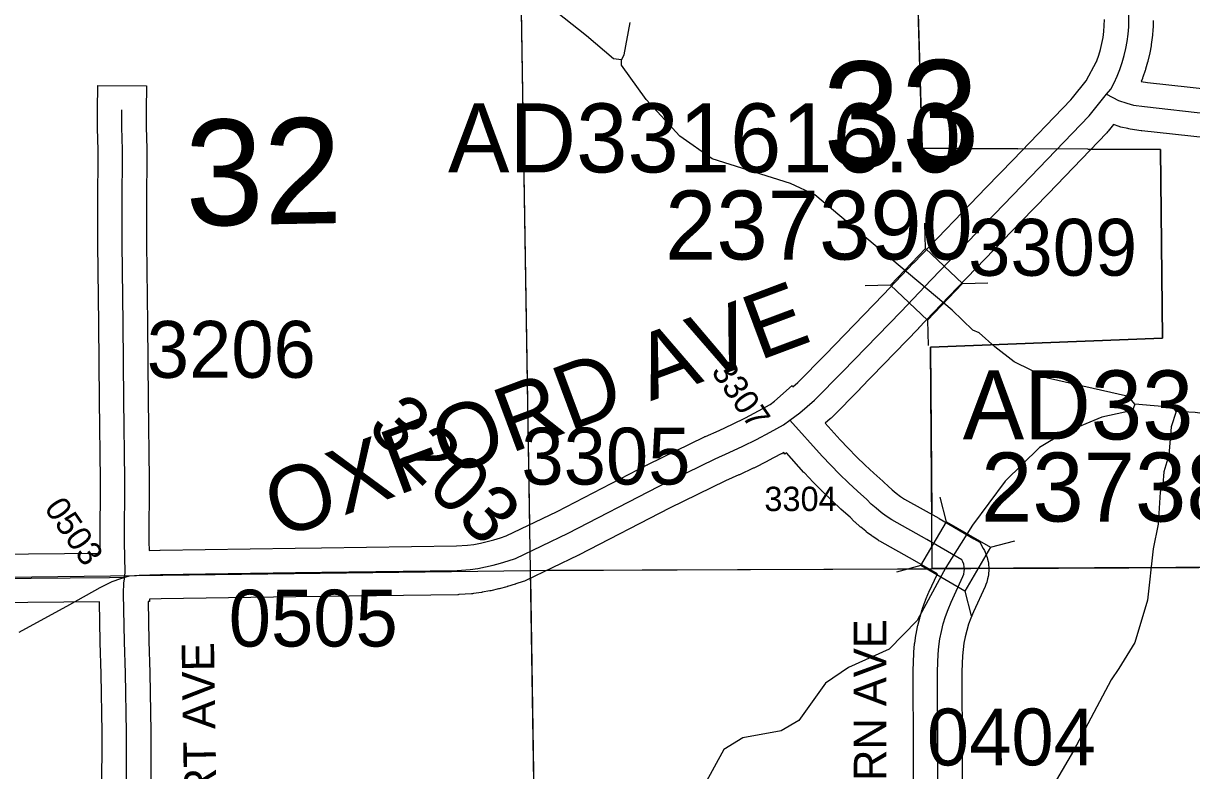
# Model space of a CAD drawing. Extents: x 23.6 to 68.7, y -63 to -29.
# Drawn here: x 46.003 to 47.442, y -45.832 to -44.911 of the extents above; entities that cross this region are included whole.
import ezdxf

# ---------------------------------------------------------------- set-up
doc = ezdxf.new("R2010")
doc.units = 0
for name, color, linetype in [('tdCoHydroRiver', 7, 'Continuous'), ('tdCoSecRdNmbr', 7, 'Continuous'), ('tdCoSecRdTxt', 7, 'Continuous'), ('tdCoSecRteBand', 7, 'Continuous'), ('tdCoSecRteCL', 7, 'Continuous'), ('tdCoSectLine', 7, 'Continuous'), ('tdCoSectLinePart', 7, 'Continuous'), ('tdCoSectNmbr', 7, 'Continuous'), ('tdCoStrucSec', 7, 'Continuous'), ('tdCoStrucSecCoName', 7, 'Continuous'), ('tdCoStrucSecFHWANum', 7, 'Continuous'), ('tdCoSurfAsphalt', 7, 'Continuous'), ('tdCoSurfConc', 7, 'Continuous'), ('tdCoSurfGravel', 7, 'Continuous'), ('tdCoSurfLNO', 7, 'Continuous'), ('tdCoTwpBndry', 7, 'Continuous'), ('tdCoTwpBndryShd', 7, 'Continuous')]:
    doc.layers.add(name, color=color, linetype=linetype)

msp = doc.modelspace()

# ---------------------------------------------------------------- linework, layer by layer
at = {"layer": 'tdCoHydroRiver'}
for points in [[(46.7396, -44.9563), (46.7301, -44.9548), (46.6967, -44.9267), (46.5279, -44.7928), (46.5247, -44.7881)], [(46.7501, -44.9104), (46.7427, -44.9499), (46.7396, -44.9563)], [(47.3725, -45.3803), (47.3645, -45.3709), (47.2648, -45.3483), (47.2235, -45.3282), (47.1997, -45.3096), (47.1805, -45.2924), (47.1726, -45.2893), (47.1471, -45.2644), (46.9782, -45.1226), (46.948, -45.1087), (46.8514, -45.0782), (46.8117, -45.0502), (46.7701, -45.0049), (46.7397, -44.9626), (46.7396, -44.9563)], [(47.3725, -45.3803), (47.3694, -45.3882), (47.3316, -45.3965), (47.2845, -45.416), (47.2547, -45.4337), (47.2125, -45.4752), (47.1721, -45.5293), (47.1395, -45.5817), (47.1039, -45.6468), (47.0695, -45.6819), (47.0193, -45.7046), (46.9911, -45.7238), (46.9584, -45.77), (46.9365, -45.7828), (46.8892, -45.7913), (46.8657, -45.8057), (46.8301, -45.8708)], [(47.4231, -45.3892), (47.4199, -45.3845), (47.3725, -45.3803)], [(47.4231, -45.3892), (47.417, -45.4082), (47.4142, -45.443), (47.4081, -45.4635), (47.4067, -45.4793), (47.4037, -45.4888), (47.4009, -45.5283), (47.395, -45.5584), (47.3877, -45.6216), (47.3725, -45.6739), (47.3524, -45.7057), (47.343, -45.72), (47.2966, -45.8073), (47.2378, -45.9074)], [(47.9026, -45.5023), (47.882, -45.4947), (47.8438, -45.4682), (47.7899, -45.4467), (47.714, -45.4302), (47.4468, -45.3905), (47.4231, -45.3892)]]:
    msp.add_lwpolyline(points, dxfattribs=at)
at = {"layer": 'tdCoSecRteBand'}
for points in [[(45.6545, -45.5678), (46.0979, -45.5638), (46.0976, -45.5509), (46.0976, -45.5505), (46.0976, -45.5501), (46.098, -45.4734), (46.0966, -45.3758), (46.0966, -45.3757), (46.0966, -45.3757), (46.0958, -45.2816), (46.0947, -45.1829), (46.0947, -45.1828), (46.0947, -45.1826), (46.0947, -45.1368), (46.0947, -45.1367), (46.0947, -45.1366), (46.0951, -45.0674), (46.0941, -45.0403), (46.0941, -45.0396), (46.0941, -45.0389), (46.0943, -45.0177), (46.0946, -44.9877), (46.1546, -44.9883), (46.1543, -45.0183), (46.1541, -45.0388), (46.1551, -45.0658), (46.1551, -45.0665), (46.1551, -45.0671), (46.1547, -45.1369), (46.1547, -45.1825), (46.1558, -45.281), (46.1558, -45.281), (46.1558, -45.281), (46.1566, -45.375), (46.158, -45.4728), (46.158, -45.4731), (46.158, -45.4734), (46.1576, -45.55), (46.1578, -45.5605), (46.171, -45.5601), (46.1712, -45.5601), (46.1715, -45.5601), (46.3377, -45.5578), (46.3378, -45.5578), (46.3378, -45.5578), (46.3703, -45.5574), (46.5364, -45.555), (46.55, -45.5541), (46.5577, -45.553), (46.5661, -45.5514), (46.5744, -45.5495), (46.5826, -45.5474), (46.5908, -45.5449), (46.5977, -45.5425), (46.6606, -45.5126), (46.7715, -45.4551), (46.7718, -45.4549), (46.7721, -45.4548), (46.842, -45.4206), (46.8426, -45.4203), (46.8432, -45.42), (46.86, -45.4127), (46.8764, -45.405), (46.8926, -45.397), (46.9085, -45.3886), (46.9229, -45.3807), (46.9285, -45.3765), (46.9499, -45.3575), (46.951, -45.3588), (46.9572, -45.3535), (46.9906, -45.3197), (47.0625, -45.2454), (47.0996, -45.2064), (47.0997, -45.2063), (47.0998, -45.2062), (47.1892, -45.1135), (47.1892, -45.1135), (47.1893, -45.1134), (47.2223, -45.0794), (47.2936, -45.0053), (47.2953, -45.0032), (47.3124, -44.982), (47.3252, -44.9581), (47.3254, -44.9582), (47.3256, -44.9575), (47.3281, -44.9505), (47.3301, -44.9433), (47.3318, -44.9361), (47.3332, -44.9288), (47.3341, -44.9214), (47.3347, -44.914), (47.335, -44.9064)], [(47.395, -44.9078), (47.3947, -44.9167), (47.3947, -44.9174), (47.3946, -44.9182), (47.3939, -44.9271), (47.3938, -44.9278), (47.3937, -44.9286), (47.3925, -44.9374), (47.3924, -44.9381), (47.3923, -44.9389), (47.3907, -44.9477), (47.3906, -44.9484), (47.3904, -44.9491), (47.3883, -44.9578), (47.3882, -44.9585), (47.388, -44.9592), (47.3855, -44.9678), (47.3853, -44.9685), (47.3851, -44.9692), (47.3822, -44.9777), (47.3819, -44.9784), (47.3816, -44.9791), (47.3801, -44.9829), (47.388, -44.984), (47.4669, -44.9928)], [(47.4602, -45.0525), (47.3809, -45.0436), (47.3805, -45.0436), (47.3801, -45.0435), (47.3666, -45.0416), (47.3651, -45.0414), (47.3637, -45.041), (47.3551, -45.039), (47.354, -45.0387), (47.3529, -45.0383), (47.3459, -45.036), (47.3395, -45.044), (47.3387, -45.045), (47.3378, -45.046), (47.2654, -45.1211), (47.2654, -45.1212), (47.2654, -45.1212), (47.2323, -45.1552), (47.143, -45.2478), (47.1059, -45.2868), (47.1058, -45.287), (47.1057, -45.2871), (47.0336, -45.3615), (47.0335, -45.3616), (47.0334, -45.3617), (46.999, -45.3966), (46.9981, -45.3975), (46.997, -45.3984), (46.9909, -45.4036), (47.0092, -45.4242), (47.0191, -45.4347), (47.0294, -45.4452), (47.04, -45.4554), (47.0507, -45.4654), (47.0619, -45.4753), (47.0625, -45.4758), (47.063, -45.4764), (47.0682, -45.4815), (47.0731, -45.4859), (47.0782, -45.49), (47.0834, -45.4939), (47.0884, -45.4973), (47.1307, -45.5208), (47.131, -45.521), (47.1312, -45.5211), (47.1741, -45.5461), (47.1815, -45.5504), (47.1855, -45.558), (47.187, -45.5607), (47.1879, -45.5625), (47.1886, -45.5645), (47.1897, -45.5673), (47.1904, -45.5693), (47.1908, -45.5713), (47.1914, -45.5743), (47.1919, -45.5763), (47.192, -45.5784), (47.1922, -45.5814), (47.1924, -45.5835), (47.1923, -45.5855), (47.1921, -45.5886), (47.1919, -45.5906), (47.1915, -45.5927), (47.1909, -45.5956), (47.1905, -45.5977), (47.1898, -45.5996), (47.1888, -45.6025), (47.1883, -45.6037), (47.1878, -45.6049), (47.1734, -45.6363), (47.1702, -45.6439), (47.1675, -45.6514), (47.1652, -45.659), (47.1633, -45.6667), (47.1618, -45.6746), (47.1606, -45.6824), (47.1599, -45.6902), (47.1593, -45.7098), (47.1594, -45.808), (47.1599, -45.9116)], [(47.0999, -45.9122), (47.0994, -45.8083), (47.0994, -45.8082), (47.0994, -45.8082), (47.0993, -45.7094), (47.0993, -45.7089), (47.0993, -45.7084), (47.0999, -45.6873), (47.1, -45.6864), (47.1001, -45.6854), (47.101, -45.676), (47.101, -45.6753), (47.1011, -45.6745), (47.1025, -45.6652), (47.1026, -45.6644), (47.1028, -45.6637), (47.1046, -45.6544), (47.1047, -45.6537), (47.1049, -45.6529), (47.1072, -45.6438), (47.1074, -45.643), (47.1076, -45.6423), (47.1103, -45.6333), (47.1106, -45.6326), (47.1108, -45.6319), (47.114, -45.6229), (47.1142, -45.6222), (47.1145, -45.6216), (47.1182, -45.6128), (47.1184, -45.6123), (47.1186, -45.6118), (47.129, -45.5892), (47.1013, -45.5731), (47.0581, -45.5491), (47.057, -45.5485), (47.056, -45.5478), (47.0494, -45.5433), (47.0488, -45.5429), (47.0482, -45.5425), (47.0418, -45.5378), (47.0413, -45.5373), (47.0407, -45.5369), (47.0346, -45.5319), (47.034, -45.5314), (47.0335, -45.531), (47.0276, -45.5256), (47.027, -45.5252), (47.0265, -45.5247), (47.0214, -45.5196), (47.0106, -45.51), (47.0103, -45.5098), (47.0101, -45.5095), (46.9989, -45.4991), (46.9987, -45.4989), (46.9984, -45.4987), (46.9874, -45.488), (46.9872, -45.4878), (46.987, -45.4876), (46.9762, -45.4767), (46.976, -45.4764), (46.9758, -45.4762), (46.9652, -45.4651), (46.9649, -45.4647), (46.9646, -45.4644), (46.9432, -45.4403), (46.9411, -45.4418), (46.9397, -45.4399), (46.9374, -45.4413), (46.9371, -45.4414), (46.9367, -45.4416), (46.9201, -45.4503), (46.9198, -45.4505), (46.9195, -45.4506), (46.9027, -45.459), (46.9024, -45.4591), (46.902, -45.4593), (46.885, -45.4672), (46.8847, -45.4674), (46.8844, -45.4675), (46.8678, -45.4748), (46.7988, -45.5085), (46.6878, -45.5661), (46.6874, -45.5663), (46.6869, -45.5665), (46.622, -45.5974), (46.6204, -45.5982), (46.6188, -45.5987), (46.6097, -45.6018), (46.6092, -45.602), (46.6087, -45.6022), (46.5995, -45.6049), (46.5989, -45.6051), (46.5984, -45.6052), (46.5891, -45.6077), (46.5886, -45.6078), (46.5881, -45.6079), (46.5787, -45.6101), (46.5782, -45.6102), (46.5776, -45.6103), (46.5682, -45.612), (46.5677, -45.6121), (46.5671, -45.6122), (46.5576, -45.6136), (46.5563, -45.6138), (46.5551, -45.6139), (46.5394, -45.6149), (46.5387, -45.615), (46.538, -45.615), (46.3711, -45.6174), (46.3711, -45.6174), (46.371, -45.6174), (46.3385, -45.6178), (46.1726, -45.6201), (46.1581, -45.6205), (46.1582, -45.6232), (46.1566, -45.6232), (46.1576, -45.6723), (46.1586, -45.7108), (46.1586, -45.7109), (46.1586, -45.7111), (46.1599, -45.784), (46.1599, -45.7843), (46.1599, -45.7846), (46.1597, -45.8606)], [(46.0997, -45.8607), (46.0999, -45.7848), (46.0986, -45.7123), (46.0976, -45.6738), (46.0976, -45.6737), (46.0976, -45.6736), (46.0966, -45.6238), (45.6555, -45.6278)]]:
    msp.add_lwpolyline(points, dxfattribs=at)
at = {"layer": 'tdCoSecRteCL'}
for points in [[(47.3375, -44.9987), (47.3426, -44.9923), (47.3468, -44.9844), (47.3505, -44.9762), (47.3538, -44.968), (47.3567, -44.9595), (47.3591, -44.9509), (47.3612, -44.9422), (47.3628, -44.9335), (47.364, -44.9246), (47.3647, -44.9157), (47.365, -44.9068), (47.3647, -44.7942), (47.3637, -44.661), (47.3629, -44.5712)], [(46.9474, -45.3999), (46.9594, -45.391), (46.9777, -45.3755), (47.012, -45.3407), (47.0842, -45.2662), (47.1213, -45.2271), (47.2108, -45.1343), (47.2438, -45.1003), (47.3162, -45.0252), (47.3375, -44.9987)], [(47.3375, -44.9987), (47.3521, -45.0064), (47.3623, -45.0098), (47.3708, -45.0119), (47.3842, -45.0138), (47.4636, -45.0227), (47.492, -45.0258), (47.518, -45.0288), (47.537, -45.0331), (47.5589, -45.0426), (47.5896, -45.0606), (47.6063, -45.068), (47.6184, -45.0719), (47.6299, -45.0738), (47.6502, -45.0752), (47.7661, -45.0738), (47.981, -45.0703), (48.1182, -45.0683), (48.2184, -45.0676), (48.4483, -45.0646)], [(46.1279, -45.5935), (46.128, -45.5917), (46.1284, -45.5873), (46.1276, -45.5503), (46.128, -45.4732), (46.1266, -45.3754), (46.1258, -45.2813), (46.1247, -45.1826), (46.1247, -45.1368), (46.1251, -45.0669), (46.1241, -45.0392), (46.1243, -45.018)], [(46.1294, -45.593), (46.1334, -45.5917), (46.1456, -45.5909), (46.1719, -45.5901), (46.3381, -45.5878), (46.3707, -45.5874), (46.5375, -45.585), (46.5532, -45.584), (46.5627, -45.5826), (46.5721, -45.5808), (46.5815, -45.5787), (46.5908, -45.5762), (46.6, -45.5734), (46.6091, -45.5703), (46.674, -45.5394), (46.7853, -45.4817), (46.8552, -45.4475), (46.8724, -45.44), (46.8894, -45.4321), (46.9062, -45.4238), (46.9228, -45.415), (46.9392, -45.4059), (46.9474, -45.3999)], [(47.1299, -45.912), (47.1294, -45.8081), (47.1293, -45.7093), (47.1299, -45.6883), (47.1308, -45.6789), (47.1322, -45.6695), (47.134, -45.6602), (47.1363, -45.651), (47.1391, -45.642), (47.1422, -45.6331), (47.1459, -45.6243), (47.1605, -45.5924), (47.1615, -45.5896), (47.1621, -45.5866), (47.1623, -45.5836), (47.1621, -45.5805), (47.1615, -45.5776), (47.1604, -45.5747), (47.159, -45.572), (47.1161, -45.547), (47.0727, -45.5229), (47.0661, -45.5184), (47.0597, -45.5137), (47.0535, -45.5086), (47.0476, -45.5033), (47.042, -45.4977), (47.0305, -45.4876), (47.0193, -45.4771), (47.0083, -45.4665), (46.9976, -45.4556), (46.9871, -45.4445), (46.9474, -45.3999)], [(45.625, -45.5981), (46.1088, -45.5937), (46.1256, -45.5935), (46.1279, -45.5935)], [(46.1297, -45.8608), (46.1299, -45.7846), (46.1286, -45.7116), (46.1276, -45.673), (46.1264, -45.6134), (46.1268, -45.6004), (46.1279, -45.5935)]]:
    msp.add_lwpolyline(points, dxfattribs=at)
at = {"layer": 'tdCoSectLine'}
for points in [[(46.6109, -44.564), (46.6274, -45.585)], [(45.6247, -45.5981), (46.6274, -45.585)], [(46.6274, -45.585), (47.6229, -45.5808)], [(46.6274, -45.585), (46.6426, -46.5504)]]:
    msp.add_lwpolyline(points, dxfattribs=at)
at = {"layer": 'tdCoSectLinePart'}
for points in [[(46.6109, -44.564), (46.6264, -45.5287)], [(46.6477, -45.5849), (47.1176, -45.583)], [(47.1919, -45.5827), (47.6229, -45.5808)], [(46.6275, -45.5946), (46.6426, -46.5504)]]:
    msp.add_lwpolyline(points, dxfattribs=at)
at = {"layer": 'tdCoStrucSec'}
for p, q in [((47.1145, -45.1885), (47.1137, -45.1572)), ((47.0714, -45.2339), (47.0401, -45.2347)), ((47.1599, -45.2316), (47.1912, -45.2308)), ((47.1168, -45.277), (47.1176, -45.3082)), ((47.1402, -45.5251), (47.1323, -45.4948)), ((47.1943, -45.5566), (47.2246, -45.5486)), ((47.1087, -45.5792), (47.0785, -45.5872)), ((47.1628, -45.6107), (47.1708, -45.6409))]:
    msp.add_line(p, q, dxfattribs=at)
for points in [[(47.0714, -45.2339), (47.1145, -45.1885), (47.1599, -45.2316), (47.1168, -45.277)], [(47.1628, -45.6107), (47.1087, -45.5792), (47.1402, -45.5251), (47.1943, -45.5566)]]:
    msp.add_lwpolyline(points, close=True, dxfattribs=at)
at = {"layer": 'tdCoSurfAsphalt'}
msp.add_lwpolyline([(46.674, -45.5394), (46.7853, -45.4817), (46.8552, -45.4475), (46.8724, -45.44), (46.8894, -45.4321), (46.9062, -45.4238), (46.9228, -45.415), (46.9392, -45.4059), (46.9474, -45.3999), (46.9594, -45.391), (46.9777, -45.3755), (47.012, -45.3407), (47.0842, -45.2662), (47.1213, -45.2271), (47.2108, -45.1343), (47.2438, -45.1003), (47.3162, -45.0252), (47.3375, -44.9987), (47.3426, -44.9923), (47.3468, -44.9844), (47.3505, -44.9762), (47.3538, -44.968), (47.3567, -44.9595), (47.3591, -44.9509), (47.3612, -44.9422), (47.3628, -44.9335), (47.364, -44.9246), (47.3647, -44.9157), (47.365, -44.9068)], dxfattribs=at)
at = {"layer": 'tdCoSurfConc'}
for points in [[(46.1294, -45.593), (46.1334, -45.5917), (46.1456, -45.5909), (46.1719, -45.5901), (46.3381, -45.5878), (46.3707, -45.5874), (46.5375, -45.585), (46.5532, -45.584), (46.5627, -45.5826), (46.5721, -45.5808), (46.5815, -45.5787), (46.5908, -45.5762), (46.6, -45.5734), (46.6091, -45.5703), (46.674, -45.5394)], [(45.625, -45.5981), (46.1088, -45.5937), (46.1256, -45.5935), (46.1279, -45.5935)]]:
    msp.add_lwpolyline(points, dxfattribs=at)
at = {"layer": 'tdCoSurfGravel'}
for points in [[(47.3375, -44.9987), (47.3521, -45.0064), (47.3623, -45.0098), (47.3708, -45.0119), (47.3842, -45.0138), (47.4636, -45.0227), (47.492, -45.0258), (47.518, -45.0288), (47.537, -45.0331), (47.5589, -45.0426), (47.5896, -45.0606), (47.6063, -45.068), (47.6184, -45.0719), (47.6299, -45.0738), (47.6502, -45.0752), (47.7661, -45.0738), (47.981, -45.0703), (48.1182, -45.0683), (48.2184, -45.0676), (48.4483, -45.0646)], [(46.128, -45.5917), (46.1284, -45.5873), (46.1276, -45.5503), (46.128, -45.4732), (46.1266, -45.3754), (46.1258, -45.2813), (46.1247, -45.1826), (46.1247, -45.1368), (46.1251, -45.0669), (46.1241, -45.0392), (46.1243, -45.018)], [(47.1299, -45.912), (47.1294, -45.8081), (47.1293, -45.7093), (47.1299, -45.6883), (47.1308, -45.6789), (47.1322, -45.6695), (47.134, -45.6602), (47.1363, -45.651), (47.1391, -45.642), (47.1422, -45.6331), (47.1459, -45.6243), (47.1605, -45.5924), (47.1615, -45.5896), (47.1621, -45.5866), (47.1623, -45.5836), (47.1621, -45.5805), (47.1615, -45.5776), (47.1604, -45.5747), (47.159, -45.572), (47.1161, -45.547), (47.0727, -45.5229), (47.0661, -45.5184), (47.0597, -45.5137), (47.0535, -45.5086), (47.0476, -45.5033), (47.042, -45.4977), (47.0305, -45.4876), (47.0193, -45.4771), (47.0083, -45.4665), (46.9976, -45.4556), (46.9871, -45.4445), (46.9474, -45.3999)], [(46.1297, -45.8608), (46.1299, -45.7846), (46.1286, -45.7116), (46.1276, -45.673), (46.1264, -45.6134), (46.1268, -45.6004), (46.1279, -45.5935), (46.128, -45.5917)]]:
    msp.add_lwpolyline(points, dxfattribs=at)
at = {"layer": 'tdCoSurfLNO'}
for p, q in [((46.0973, -45.606), (46.1121, -45.5989)), ((46.1121, -45.5989), (46.1228, -45.5952)), ((46.1228, -45.5952), (46.1256, -45.5942)), ((46.1256, -45.5942), (46.1279, -45.5935)), ((46.1279, -45.5935), (46.1294, -45.593)), ((46.0601, -45.6271), (46.0973, -45.606)), ((45.9978, -45.6612), (46.0601, -45.6271))]:
    msp.add_line(p, q, dxfattribs=at)
at = {"layer": 'tdCoTwpBndry'}
for points in [[(44.6442, -44.1085), (45.6093, -44.0973), (45.6121, -44.5846), (46.6109, -44.564), (47.0956, -44.5667), (47.1104, -45.065), (47.2282, -45.066)], [(47.3143, -45.0663), (47.404, -45.0665), (47.4063, -45.2992), (47.1206, -45.3103), (47.122, -45.515)], [(47.1919, -45.5827), (47.6241, -45.5808), (48.1595, -45.5695), (48.1676, -46.01), (48.3914, -45.9999), (48.4052, -46.2647), (48.6282, -46.263), (48.63, -46.5299), (49.1013, -46.5194)]]:
    msp.add_lwpolyline(points, dxfattribs=at)
at = {"layer": 'tdCoTwpBndryShd'}
msp.add_lwpolyline([(50.63, -46.4962), (49.6188, -46.5078), (48.63, -46.5299), (48.6282, -46.263), (48.4052, -46.2647), (48.3914, -45.9999), (48.1676, -46.01), (48.1595, -45.5695), (47.6229, -45.5808), (47.1225, -45.5829), (47.1206, -45.3103), (47.4063, -45.2992), (47.404, -45.0665), (47.3143, -45.0663), (47.2282, -45.066), (47.1104, -45.065), (47.0959, -44.5667), (46.6109, -44.564), (45.6121, -44.5846), (45.6093, -44.0972), (44.6442, -44.1085), (44.6364, -44.1086)], dxfattribs=at)

# ---------------------------------------------------------------- texts
at = {"layer": 'tdCoSecRdNmbr'}
for s, height, rotation, p in [('3309', 0.07, 0.0367, (47.167, -45.2222)), ('3206', 0.07, 0.0359, (46.1549, -45.3479)), ('3307', 0.03, 304.5131, (46.8496, -45.3402)), ('3203', 0.07, 315.0354, (46.4244, -45.4109)), ('3305', 0.07, 0.0363, (46.6165, -45.4794)), ('3304', 0.03, 0.0365, (46.9158, -45.512)), ('0503', 0.03, 304.5131, (46.0277, -45.5084)), ('0505', 0.07, 0.036, (46.2559, -45.6789)), ('0404', 0.07, 0.0367, (47.1161, -45.8253))]:
    msp.add_text(s, height=height, rotation=rotation, dxfattribs=at).set_placement(p)
at = {"layer": 'tdCoSecRdTxt'}
for s, height, rotation, p in [('OXFORD AVE', 0.08, 20.4421, (46.319, -45.547)), ('OSBURN AVE', 0.04, 90, (47.066, -45.996)), ('NEWPORT AVE', 0.04, 90.9233, (46.2441, -46.0686))]:
    msp.add_text(s, height=height, rotation=rotation, dxfattribs=at).set_placement(p)
at = {"layer": 'tdCoSectNmbr'}
for s, rotation, p in [('33', 1.0365, (46.9889, -45.0892)), ('32', 1.0359, (46.2031, -45.1607))]:
    msp.add_text(s, height=0.13, rotation=rotation, dxfattribs=at).set_placement(p)
at = {"layer": 'tdCoStrucSecCoName'}
for s, p in [('AD331616.0', (46.526, -45.0949)), ('AD331617.0', (47.1602, -45.4238))]:
    msp.add_text(s, height=0.085, dxfattribs=at).set_placement(p)
at = {"layer": 'tdCoStrucSecFHWANum'}
for s, p in [('237390', (46.7935, -45.2022)), ('237380', (47.1828, -45.5249))]:
    msp.add_text(s, height=0.085, dxfattribs=at).set_placement(p)

doc.saveas('drawing.dxf')
